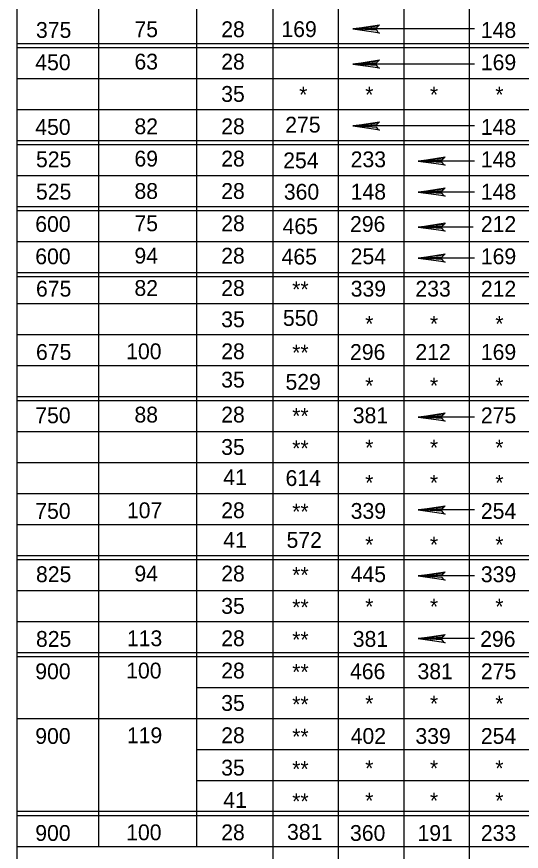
# Model space of a CAD drawing. Extents: x -22562 to -18409, y 3991 to 7171.
# Drawn here: x -21123.7 to -21032.1, y 6660.5 to 6812.1 of the extents above; entities that cross this region are included whole.
import ezdxf

# ---------------------------------------------------------------- set-up
doc = ezdxf.new("R2010")
doc.units = 0
doc.layers.add('2', color=7, linetype='Continuous')

msp = doc.modelspace()

# ---------------------------------------------------------------- linework, layer by layer
at = {"layer": '2'}
for p, q in [((-21123.72, 6891.87), (-21123.72, 6549.24)), ((-21077.22, 6884.12), (-21077.22, 6549.24)), ((-21108.85, 6878.37), (-21108.85, 6661.37)), ((-21091.1, 6878.37), (-21091.1, 6661.37)), ((-21065.35, 6878.37), (-21065.35, 6549.24)), ((-21053.47, 6878.37), (-21053.47, 6549.24)), ((-21041.6, 6878.37), (-21041.6, 6549.24)), ((-21040.6, 6809.87), (-21062.72, 6809.87)), ((-21123.72, 6807.24), (-20935.22, 6807.24)), ((-21123.72, 6806.49), (-20935.22, 6806.49)), ((-21040.6, 6803.49), (-21062.72, 6803.49)), ((-21123.72, 6800.87), (-20935.22, 6800.87)), ((-21123.72, 6795.24), (-20935.22, 6795.24)), ((-21040.6, 6792.24), (-21062.72, 6792.24)), ((-21123.72, 6789.62), (-20935.22, 6789.62)), ((-21123.72, 6788.87), (-20935.22, 6788.87)), ((-21040.6, 6785.87), (-21050.85, 6785.87)), ((-21123.72, 6783.24), (-20935.22, 6783.24)), ((-21040.6, 6780.24), (-21050.85, 6780.24)), ((-21123.72, 6777.62), (-20935.22, 6777.62)), ((-21123.72, 6776.87), (-20935.22, 6776.87)), ((-21040.85, 6773.87), (-21050.85, 6773.87)), ((-21123.72, 6771.24), (-20935.22, 6771.24)), ((-21040.6, 6768.24), (-21050.85, 6768.24)), ((-21123.72, 6765.62), (-20935.22, 6765.62)), ((-21123.72, 6764.87), (-20935.22, 6764.87)), ((-21123.72, 6759.99), (-20935.22, 6759.99)), ((-21123.72, 6754.37), (-20935.22, 6754.37)), ((-21123.72, 6748.74), (-20935.22, 6748.74)), ((-21123.72, 6743.12), (-20935.22, 6743.12)), ((-21123.72, 6742.37), (-20935.22, 6742.37)), ((-21040.6, 6739.37), (-21050.85, 6739.37)), ((-21123.72, 6736.74), (-20935.22, 6736.74)), ((-21123.72, 6731.12), (-20935.22, 6731.12)), ((-21123.72, 6725.49), (-20935.22, 6725.49)), ((-21040.6, 6722.49), (-21050.85, 6722.49)), ((-21123.72, 6719.87), (-20935.22, 6719.87)), ((-21123.72, 6714.24), (-20935.22, 6714.24)), ((-21123.72, 6713.49), (-20935.22, 6713.49)), ((-21040.6, 6710.49), (-21050.85, 6710.49)), ((-21123.72, 6707.87), (-20935.22, 6707.87)), ((-21123.72, 6702.24), (-20935.22, 6702.24)), ((-21040.6, 6699.12), (-21050.85, 6699.12)), ((-21123.72, 6696.62), (-20935.22, 6696.62)), ((-21123.72, 6695.87), (-20935.22, 6695.87)), ((-21091.1, 6690.24), (-20935.22, 6690.24)), ((-21123.72, 6684.62), (-20935.22, 6684.62)), ((-21091.1, 6678.99), (-20935.22, 6678.99)), ((-21091.1, 6673.37), (-20935.22, 6673.37)), ((-21123.72, 6667.74), (-20935.22, 6667.74)), ((-21123.72, 6666.99), (-20935.22, 6666.99)), ((-21123.72, 6661.37), (-20935.22, 6661.37))]:
    msp.add_line(p, q, dxfattribs=at)
for points in [[(-21058.1, 6809.24), (-21058.35, 6809.62), (-21062.72, 6809.87), (-21058.1, 6809.24), (-21057.85, 6809.12), (-21062.72, 6809.87), (-21058.35, 6810.12), (-21058.1, 6810.37), (-21062.72, 6809.87), (-21057.85, 6810.62), (-21058.1, 6810.37)], [(-21058.1, 6809.24), (-21058.35, 6809.62), (-21062.72, 6809.87), (-21058.1, 6809.24), (-21057.85, 6809.12), (-21062.72, 6809.87), (-21058.35, 6810.12), (-21058.1, 6810.37), (-21062.72, 6809.87), (-21057.85, 6810.62), (-21058.1, 6810.37)], [(-21058.1, 6802.87), (-21058.35, 6803.24), (-21062.72, 6803.49), (-21058.1, 6802.87), (-21057.85, 6802.74), (-21062.72, 6803.49), (-21058.35, 6803.74), (-21058.1, 6803.99), (-21062.72, 6803.49), (-21057.85, 6804.24), (-21058.1, 6803.99)], [(-21058.1, 6802.87), (-21058.35, 6803.24), (-21062.72, 6803.49), (-21058.1, 6802.87), (-21057.85, 6802.74), (-21062.72, 6803.49), (-21058.35, 6803.74), (-21058.1, 6803.99), (-21062.72, 6803.49), (-21057.85, 6804.24), (-21058.1, 6803.99)], [(-21058.1, 6791.62), (-21058.35, 6791.99), (-21062.72, 6792.24), (-21058.1, 6791.62), (-21057.85, 6791.49), (-21062.72, 6792.24), (-21058.35, 6792.49), (-21058.1, 6792.74), (-21062.72, 6792.24), (-21057.85, 6792.99), (-21058.1, 6792.74)], [(-21058.1, 6791.62), (-21058.35, 6791.99), (-21062.72, 6792.24), (-21058.1, 6791.62), (-21057.85, 6791.49), (-21062.72, 6792.24), (-21058.35, 6792.49), (-21058.1, 6792.74), (-21062.72, 6792.24), (-21057.85, 6792.99), (-21058.1, 6792.74)], [(-21046.22, 6785.24), (-21046.47, 6785.62), (-21050.85, 6785.87), (-21046.22, 6785.24), (-21045.97, 6785.12), (-21050.85, 6785.87), (-21046.47, 6786.12), (-21046.22, 6786.37), (-21050.85, 6785.87), (-21045.97, 6786.62), (-21046.22, 6786.37)], [(-21046.22, 6785.24), (-21046.47, 6785.62), (-21050.85, 6785.87), (-21046.22, 6785.24), (-21045.97, 6785.12), (-21050.85, 6785.87), (-21046.47, 6786.12), (-21046.22, 6786.37), (-21050.85, 6785.87), (-21045.97, 6786.62), (-21046.22, 6786.37)], [(-21046.22, 6779.62), (-21046.47, 6779.99), (-21050.85, 6780.24), (-21046.22, 6779.62), (-21045.97, 6779.49), (-21050.85, 6780.24), (-21046.47, 6780.49), (-21046.22, 6780.74), (-21050.85, 6780.24), (-21045.97, 6780.99), (-21046.22, 6780.74)], [(-21046.22, 6779.62), (-21046.47, 6779.99), (-21050.85, 6780.24), (-21046.22, 6779.62), (-21045.97, 6779.49), (-21050.85, 6780.24), (-21046.47, 6780.49), (-21046.22, 6780.74), (-21050.85, 6780.24), (-21045.97, 6780.99), (-21046.22, 6780.74)], [(-21046.22, 6773.24), (-21046.47, 6773.62), (-21050.85, 6773.87), (-21046.22, 6773.24), (-21045.97, 6773.12), (-21050.85, 6773.87), (-21046.47, 6774.12), (-21046.22, 6774.37), (-21050.85, 6773.87), (-21045.97, 6774.62), (-21046.22, 6774.37)], [(-21046.22, 6773.24), (-21046.47, 6773.62), (-21050.85, 6773.87), (-21046.22, 6773.24), (-21045.97, 6773.12), (-21050.85, 6773.87), (-21046.47, 6774.12), (-21046.22, 6774.37), (-21050.85, 6773.87), (-21045.97, 6774.62), (-21046.22, 6774.37)], [(-21046.22, 6767.62), (-21046.47, 6767.99), (-21050.85, 6768.24), (-21046.22, 6767.62), (-21045.97, 6767.49), (-21050.85, 6768.24), (-21046.47, 6768.49), (-21046.22, 6768.74), (-21050.85, 6768.24), (-21045.97, 6768.99), (-21046.22, 6768.74)], [(-21046.22, 6767.62), (-21046.47, 6767.99), (-21050.85, 6768.24), (-21046.22, 6767.62), (-21045.97, 6767.49), (-21050.85, 6768.24), (-21046.47, 6768.49), (-21046.22, 6768.74), (-21050.85, 6768.24), (-21045.97, 6768.99), (-21046.22, 6768.74)], [(-21046.22, 6738.74), (-21046.47, 6739.12), (-21050.85, 6739.37), (-21046.22, 6738.74), (-21045.97, 6738.62), (-21050.85, 6739.37), (-21046.47, 6739.62), (-21046.22, 6739.87), (-21050.85, 6739.37), (-21045.97, 6740.12), (-21046.22, 6739.87)], [(-21046.22, 6738.74), (-21046.47, 6739.12), (-21050.85, 6739.37), (-21046.22, 6738.74), (-21045.97, 6738.62), (-21050.85, 6739.37), (-21046.47, 6739.62), (-21046.22, 6739.87), (-21050.85, 6739.37), (-21045.97, 6740.12), (-21046.22, 6739.87)], [(-21046.22, 6721.87), (-21046.47, 6722.24), (-21050.85, 6722.49), (-21046.22, 6721.87), (-21045.97, 6721.74), (-21050.85, 6722.49), (-21046.47, 6722.74), (-21046.22, 6722.99), (-21050.85, 6722.49), (-21045.97, 6723.24), (-21046.22, 6722.99)], [(-21046.22, 6721.87), (-21046.47, 6722.24), (-21050.85, 6722.49), (-21046.22, 6721.87), (-21045.97, 6721.74), (-21050.85, 6722.49), (-21046.47, 6722.74), (-21046.22, 6722.99), (-21050.85, 6722.49), (-21045.97, 6723.24), (-21046.22, 6722.99)], [(-21046.22, 6709.87), (-21046.47, 6710.24), (-21050.85, 6710.49), (-21046.22, 6709.87), (-21045.97, 6709.74), (-21050.85, 6710.49), (-21046.47, 6710.74), (-21046.22, 6710.99), (-21050.85, 6710.49), (-21045.97, 6711.24), (-21046.22, 6710.99)], [(-21046.22, 6709.87), (-21046.47, 6710.24), (-21050.85, 6710.49), (-21046.22, 6709.87), (-21045.97, 6709.74), (-21050.85, 6710.49), (-21046.47, 6710.74), (-21046.22, 6710.99), (-21050.85, 6710.49), (-21045.97, 6711.24), (-21046.22, 6710.99)], [(-21046.22, 6698.49), (-21046.47, 6698.87), (-21050.85, 6699.12), (-21046.22, 6698.49), (-21045.97, 6698.37), (-21050.85, 6699.12), (-21046.47, 6699.37), (-21046.22, 6699.62), (-21050.85, 6699.12), (-21045.97, 6699.87), (-21046.22, 6699.62)], [(-21046.22, 6698.49), (-21046.47, 6698.87), (-21050.85, 6699.12), (-21046.22, 6698.49), (-21045.97, 6698.37), (-21050.85, 6699.12), (-21046.47, 6699.37), (-21046.22, 6699.62), (-21050.85, 6699.12), (-21045.97, 6699.87), (-21046.22, 6699.62)]]:
    msp.add_lwpolyline(points, dxfattribs=at)

# ---------------------------------------------------------------- texts
for s, height, p in [('375', 2.875, (-21120.22, 6808.24)), ('75', 2.875, (-21102.35, 6808.37)), ('28', 2.875, (-21086.6, 6808.37)), ('169', 2.875, (-21075.67, 6808.39)), ('148', 2.875, (-21039.47, 6808.24)), ('450', 2.875, (-21120.35, 6802.37)), ('63', 2.875, (-21102.35, 6802.49)), ('28', 2.875, (-21086.6, 6802.49)), ('169', 2.875, (-21039.47, 6802.37)), ('35', 2.875, (-21086.6, 6796.62)), ('*', 2.87, (-21072.46, 6796.49)), ('*', 2.87, (-21060.47, 6796.49)), ('*', 2.87, (-21048.72, 6796.49)), ('*', 2.87, (-21036.85, 6796.49)), ('275', 2.875, (-21074.98, 6791.04)), ('450', 2.875, (-21120.35, 6790.62)), ('82', 2.875, (-21102.35, 6790.74)), ('28', 2.875, (-21086.6, 6790.74)), ('148', 2.875, (-21039.47, 6790.62)), ('69', 2.875, (-21102.35, 6784.87)), ('28', 2.875, (-21086.6, 6784.87)), ('525', 2.875, (-21120.22, 6784.74)), ('254', 2.875, (-21075.35, 6784.55)), ('233', 2.875, (-21063.1, 6784.74)), ('148', 2.875, (-21039.47, 6784.74)), ('525', 2.875, (-21120.22, 6778.87)), ('88', 2.875, (-21102.35, 6778.99)), ('28', 2.875, (-21086.6, 6778.99)), ('360', 2.875, (-21075.23, 6778.85)), ('148', 2.875, (-21063.1, 6778.87)), ('148', 2.875, (-21039.47, 6778.87)), ('600', 2.875, (-21120.35, 6772.99)), ('75', 2.875, (-21102.35, 6773.12)), ('28', 2.875, (-21086.6, 6773.12)), ('296', 2.875, (-21063.22, 6772.99)), ('212', 2.875, (-21039.47, 6772.99)), ('465', 2.875, (-21075.46, 6772.6)), ('600', 2.875, (-21120.35, 6767.12)), ('94', 2.875, (-21102.35, 6767.24)), ('28', 2.875, (-21086.6, 6767.24)), ('465', 2.875, (-21075.64, 6767.07)), ('254', 2.875, (-21063.1, 6767.12)), ('169', 2.875, (-21039.47, 6767.12)), ('675', 2.875, (-21120.22, 6761.24)), ('82', 2.875, (-21102.35, 6761.37)), ('28', 2.875, (-21086.6, 6761.37)), ('**', 2.875, (-21073.72, 6761.12)), ('339', 2.875, (-21063.1, 6761.24)), ('233', 2.875, (-21051.35, 6761.24)), ('212', 2.875, (-21039.47, 6761.24)), ('35', 2.875, (-21086.6, 6755.68)), ('550', 2.875, (-21075.4, 6755.92)), ('*', 2.87, (-21060.47, 6754.87)), ('*', 2.87, (-21048.72, 6754.87)), ('*', 2.87, (-21036.85, 6754.87)), ('675', 2.875, (-21120.22, 6749.74)), ('100', 2.875, (-21103.85, 6749.87)), ('28', 2.875, (-21086.6, 6749.87)), ('**', 2.875, (-21073.72, 6749.62)), ('296', 2.875, (-21063.22, 6749.74)), ('212', 2.875, (-21051.35, 6749.74)), ('169', 2.875, (-21039.47, 6749.74)), ('35', 2.875, (-21086.6, 6744.72)), ('529', 2.875, (-21074.93, 6744.32)), ('*', 2.87, (-21060.47, 6743.62)), ('*', 2.87, (-21048.72, 6743.62)), ('*', 2.87, (-21036.85, 6743.62)), ('750', 2.875, (-21120.35, 6738.24)), ('88', 2.875, (-21102.35, 6738.37)), ('28', 2.875, (-21086.6, 6738.37)), ('**', 2.875, (-21073.72, 6738.12)), ('381', 2.875, (-21062.72, 6738.24)), ('275', 2.875, (-21039.47, 6738.24)), ('35', 2.875, (-21086.6, 6732.49)), ('**', 2.875, (-21073.72, 6732.24)), ('*', 2.87, (-21060.47, 6732.37)), ('*', 2.87, (-21048.72, 6732.37)), ('*', 2.87, (-21036.85, 6732.37)), ('41', 2.875, (-21086.22, 6726.99)), ('614', 2.875, (-21074.92, 6726.84)), ('*', 2.87, (-21060.47, 6725.99)), ('*', 2.87, (-21048.72, 6725.99)), ('*', 2.87, (-21036.85, 6725.99)), ('750', 2.875, (-21120.35, 6720.87)), ('107', 2.875, (-21103.72, 6720.99)), ('28', 2.875, (-21086.6, 6720.99)), ('**', 2.875, (-21073.72, 6720.74)), ('339', 2.875, (-21063.1, 6720.87)), ('254', 2.875, (-21039.47, 6720.87)), ('41', 2.875, (-21086.22, 6715.62)), ('572', 2.875, (-21074.74, 6715.6)), ('*', 2.87, (-21060.47, 6714.74)), ('*', 2.87, (-21048.72, 6714.74)), ('*', 2.87, (-21036.85, 6714.74)), ('825', 2.875, (-21120.22, 6709.37)), ('94', 2.875, (-21102.35, 6709.49)), ('28', 2.875, (-21086.6, 6709.49)), ('**', 2.875, (-21073.72, 6709.24)), ('445', 2.875, (-21063.1, 6709.37)), ('339', 2.875, (-21039.47, 6709.37)), ('35', 2.875, (-21086.6, 6703.62)), ('**', 2.875, (-21073.72, 6703.37)), ('*', 2.87, (-21060.47, 6703.49)), ('*', 2.87, (-21048.72, 6703.49)), ('*', 2.87, (-21036.85, 6703.49)), ('825', 2.875, (-21120.22, 6697.62)), ('113', 2.875, (-21103.72, 6697.74)), ('28', 2.875, (-21086.6, 6697.74)), ('**', 2.875, (-21073.72, 6697.49)), ('381', 2.875, (-21062.72, 6697.62)), ('296', 2.875, (-21039.6, 6697.62)), ('900', 2.875, (-21120.35, 6691.74)), ('100', 2.875, (-21103.85, 6691.87)), ('28', 2.875, (-21086.6, 6691.87)), ('**', 2.875, (-21073.72, 6691.62)), ('466', 2.875, (-21063.22, 6691.74)), ('381', 2.875, (-21050.97, 6691.74)), ('275', 2.875, (-21039.47, 6691.74)), ('35', 2.875, (-21086.6, 6685.99)), ('**', 2.875, (-21073.72, 6685.74)), ('*', 2.87, (-21060.47, 6685.87)), ('*', 2.87, (-21048.72, 6685.87)), ('*', 2.87, (-21036.85, 6685.87)), ('900', 2.875, (-21120.35, 6679.99)), ('119', 2.875, (-21103.72, 6680.12)), ('28', 2.875, (-21086.6, 6680.12)), ('**', 2.875, (-21073.72, 6679.87)), ('402', 2.875, (-21063.1, 6679.99)), ('339', 2.875, (-21051.35, 6679.99)), ('254', 2.875, (-21039.47, 6679.99)), ('35', 2.875, (-21086.6, 6674.24)), ('*', 2.87, (-21060.47, 6674.12)), ('*', 2.87, (-21048.72, 6674.12)), ('*', 2.87, (-21036.85, 6674.12)), ('**', 2.875, (-21073.72, 6673.99)), ('41', 2.875, (-21086.22, 6668.37)), ('**', 2.875, (-21073.72, 6668.12)), ('*', 2.87, (-21060.47, 6668.24)), ('*', 2.87, (-21048.72, 6668.24)), ('*', 2.87, (-21036.85, 6668.24)), ('900', 2.875, (-21120.35, 6662.37)), ('100', 2.875, (-21103.85, 6662.49)), ('28', 2.875, (-21086.6, 6662.49)), ('381', 2.875, (-21074.65, 6662.56)), ('360', 2.875, (-21063.22, 6662.37)), ('191', 2.875, (-21050.97, 6662.37)), ('233', 2.875, (-21039.47, 6662.37))]:
    msp.add_text(s, height=height, dxfattribs=at).set_placement(p)

doc.saveas('drawing.dxf')
